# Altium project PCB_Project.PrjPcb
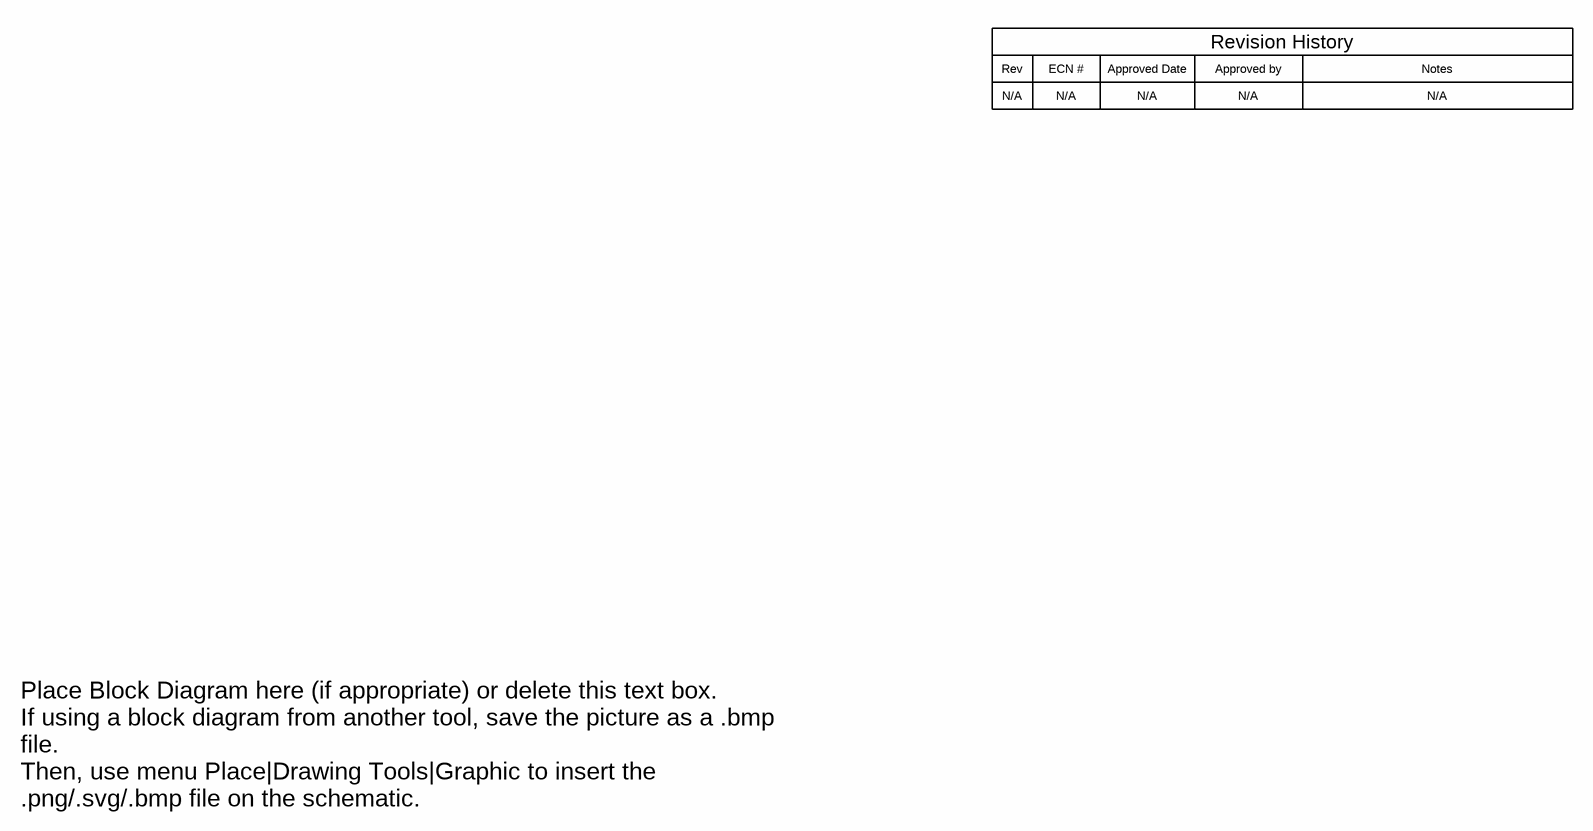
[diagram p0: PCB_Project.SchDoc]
CopyrightYear: 2018; PCB_Layout: Who did the Layout?; PCB_Rev: E1; PRJ_Customer: Public Release; PRJ_Engineer: Enter name of project lead; PRJ_Number: XXX###; PRJ_Title: Change in menu Project|Project Options|Parameters; SCH_Rev: E1; TechSupport: http://www.ti.com/support; TID: N/A
3 sheets, 133 parts. Net scope: flat (ports and power ports of the same name join across sheets).
Board file: PCB_Project.PcbDoc
Sheets:
  PCB_Project.SchDoc
  PCB_Project_BlankSheet.SchDoc
  PCB_Project_Hardware.SchDoc

## Sheet PCB_Project.SchDoc
size 431 x 279 mm; Date: Not shown in title block; ApprovedBy: Not shown in title block; CheckedBy: Not shown in title block; Author: Not shown in title block; CompanyName: Not shown in title block; Engineer: Not shown in title block; Organization: Not shown in title block; Address1: Not shown in title block; Address2: Not shown in title block; Address3: Not shown in title block; Address4: Not shown in title block; DocumentNumber: 1; Revision: Use project parameter SCH_Rev; SheetNumber: 1; SheetTotal: 3; PageSetup: Record=PageOptions¦CenterHorizontal=True¦CenterVertical=True¦PrintScale=1.00¦XCorrection=1.00¦YCorrection=1.00¦PrintKind=0¦BorderSize=5000000¦LeftOffset=0¦BottomOffset=0¦Orientation=2¦PaperLength=1000¦PaperWidth=1000¦Scale=100¦PaperSource=15¦PrintQuality=600¦MediaType=1¦DitherType=10¦PaperKind=Letter¦PrintScaleMode=1

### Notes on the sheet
- Rev
- N/A
- ECN #
- Approved Date
- Approved by
- Revision History
- Notes
- Place Block Diagram here (if appropriate) or delete this text box.
  If using a block diagram from another tool, save the picture as a .bmp file.
  Then, use menu Place|Drawing Tools|Graphic to insert the .png/.svg/.bmp file on the schematic.

## Sheet PCB_Project_BlankSheet.SchDoc
size 431 x 279 mm; Date: Not shown in title block; ApprovedBy: Not shown in title block; CheckedBy: Not shown in title block; Author: Not shown in title block; CompanyName: Not shown in title block; Engineer: Not shown in title block; Organization: Not shown in title block; Address1: Not shown in title block; Address2: Not shown in title block; Address3: Not shown in title block; Address4: Not shown in title block; DocumentNumber: 2; Revision: Use project parameter SCH_Rev; SheetNumber: 2; SheetTotal: 3; PageSetup: Record=PageOptions¦CenterHorizontal=True¦CenterVertical=True¦PrintScale=1.00¦XCorrection=1.00¦YCorrection=1.00¦PrintKind=0¦BorderSize=5000000¦LeftOffset=0¦BottomOffset=0¦Orientation=2¦PaperLength=1000¦PaperWidth=1000¦Scale=100¦PaperSource=15¦PrintQuality=600¦MediaType=1¦DitherType=10¦PaperKind=Letter¦PrintScaleMode=1
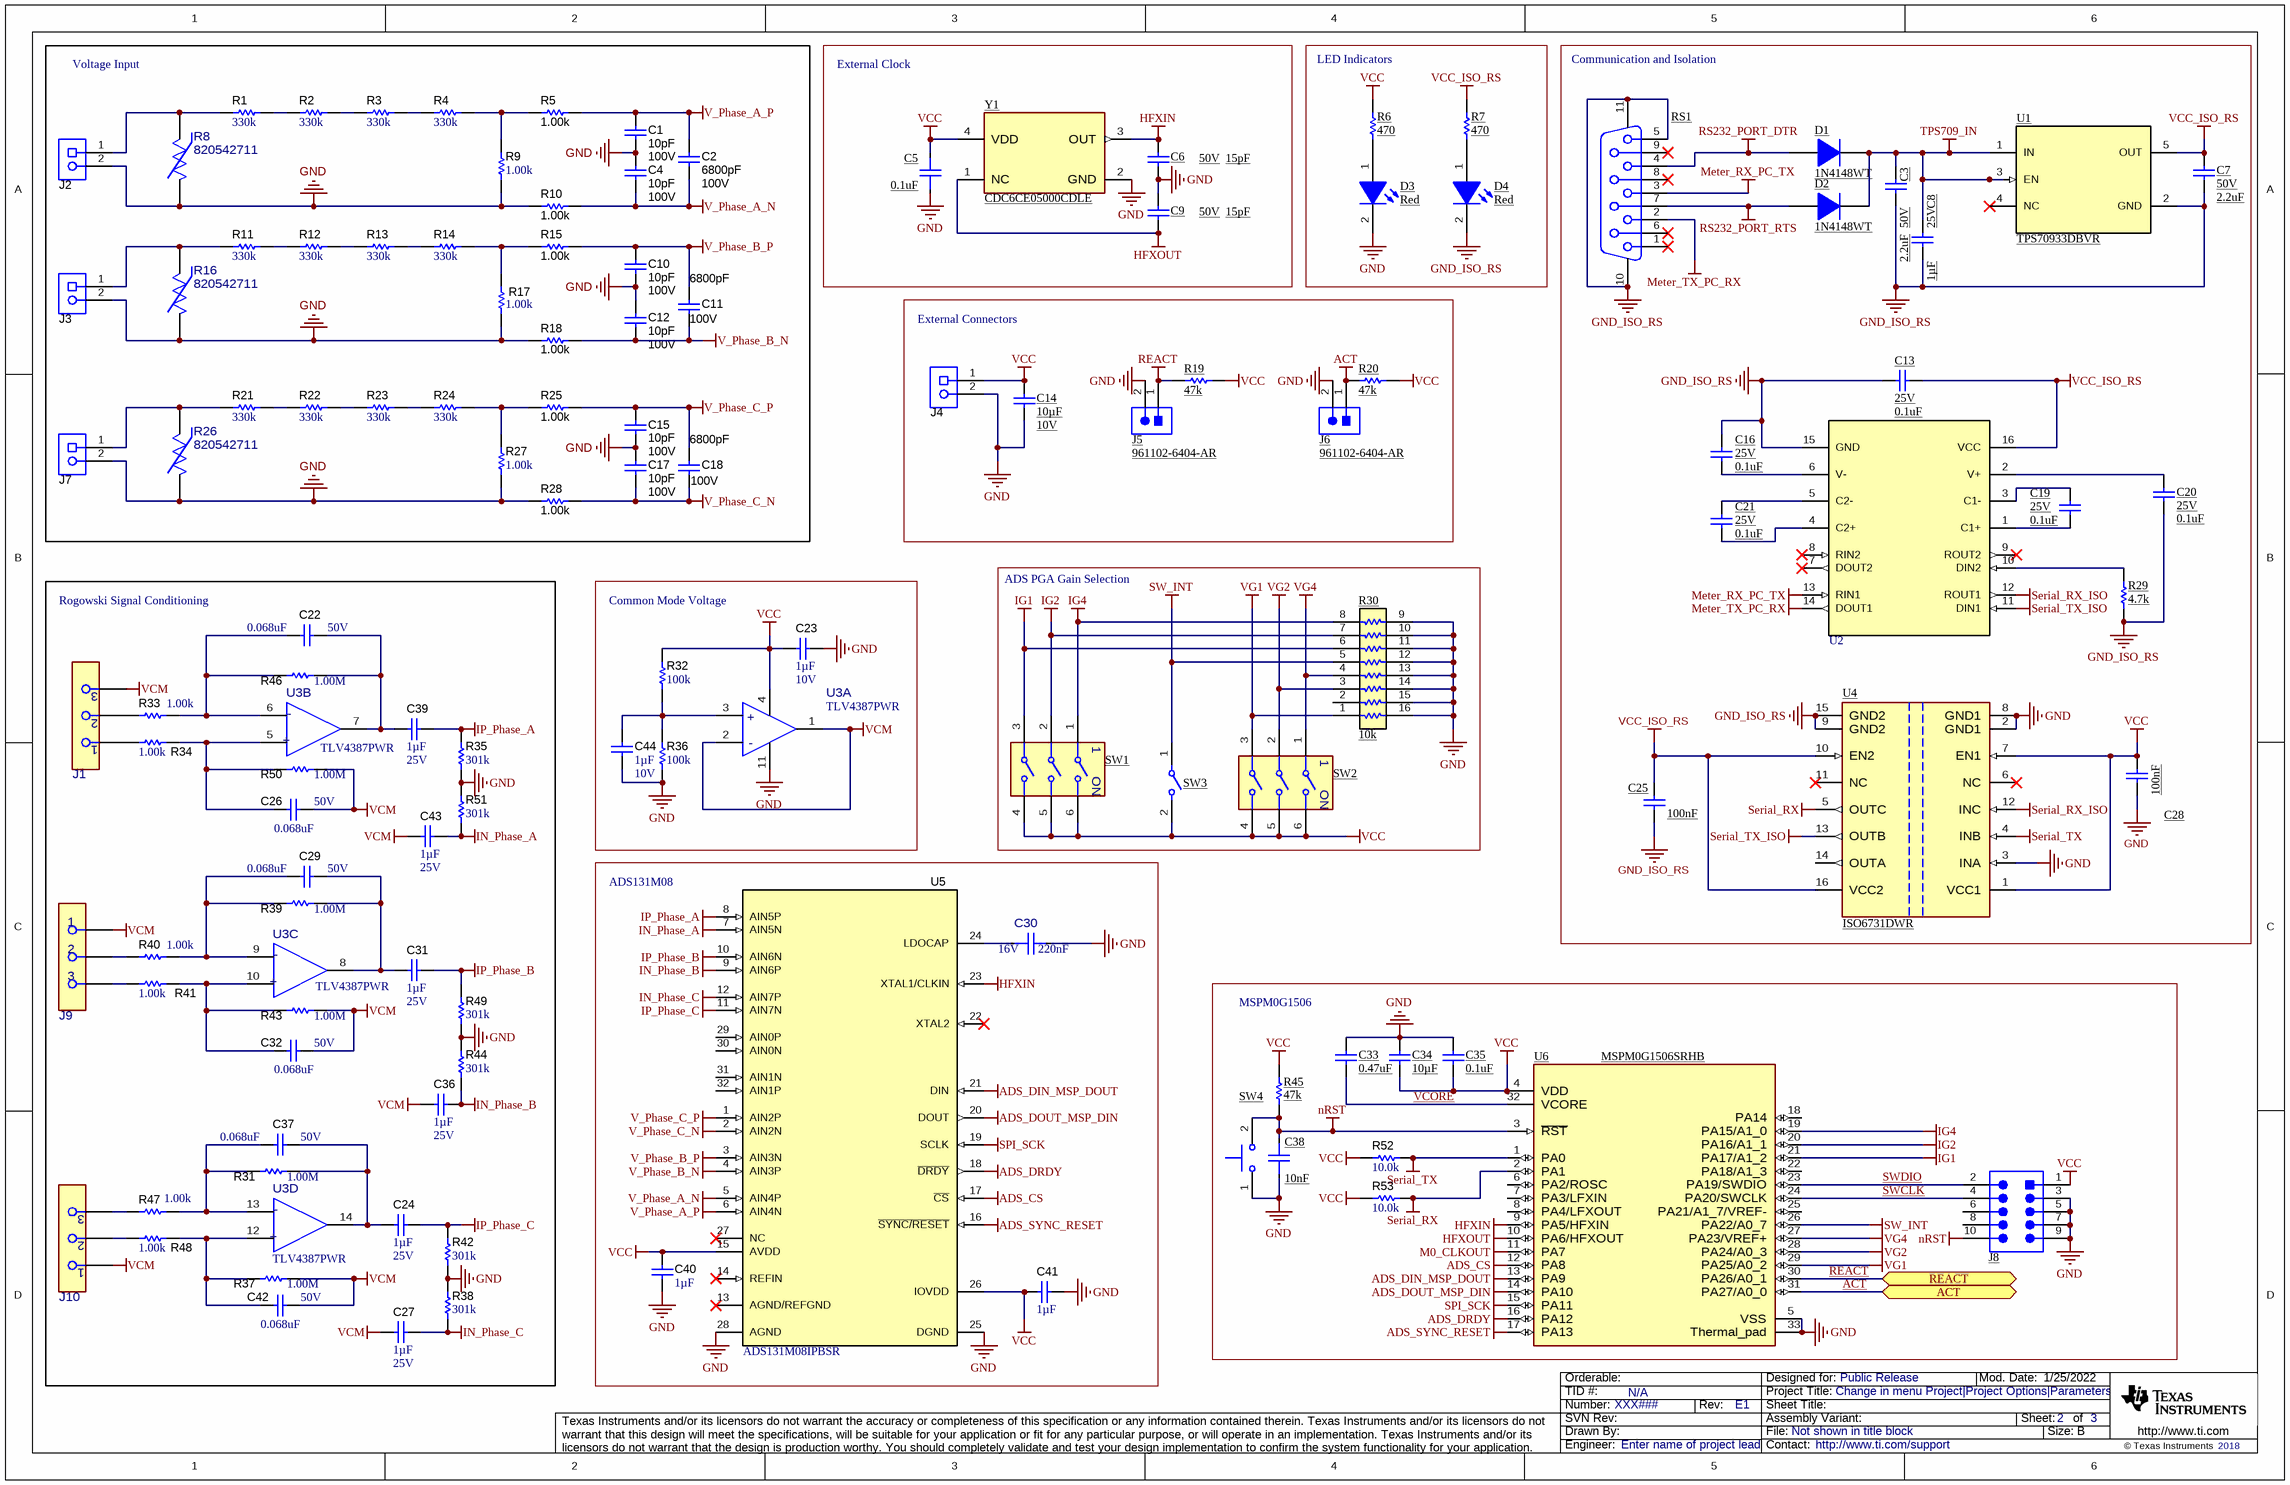
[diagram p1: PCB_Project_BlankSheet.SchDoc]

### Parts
C1  ValueDisplayed: 10pF  VDC_V: 100V  [0603]  (hidden comment: GCM1885C2A100JA16D)
C2  ValueDisplayed: 6800pF  VDC_V: 100V  [0603]  (hidden comment: CGA3EANP02A682J080AC)
C3  VDC_V: 50V  ValueDisplayed: 2.2uF  [0603]  (hidden comment: GRT188R61H225KE13D)
C4  ValueDisplayed: 10pF  VDC_V: 100V  [0603]  (hidden comment: GCM1885C2A100JA16D)
C5  ValueDisplayed: 0.1uF  [FP-885012205018_0402-MFG]  (hidden comment: 885012205018)
C6  VDC_V: 50V  ValueDisplayed: 15pF  [0402]  (hidden comment: GRM1555C1H150JA01D)
C7  VDC_V: 50V  ValueDisplayed: 2.2uF  [0603]  (hidden comment: GRT188R61H225KE13D)
C8  VDC_V: 25V  ValueDisplayed: 1µF  [0603]  (hidden comment: CGA3E1X7R1E105M080AC)
C9  VDC_V: 50V  ValueDisplayed: 15pF  [0402]  (hidden comment: GRM1555C1H150JA01D)
C10  ValueDisplayed: 10pF  VDC_V: 100V  [0603]  (hidden comment: GCM1885C2A100JA16D)
C11  ValueDisplayed: 6800pF  VDC_V: 100V  [0603]  (hidden comment: CGA3EANP02A682J080AC)
C12  ValueDisplayed: 10pF  VDC_V: 100V  [0603]  (hidden comment: GCM1885C2A100JA16D)
C13  VDC_V: 25V  ValueDisplayed: 0.1uF  [0603]  (hidden comment: CGA3E2X8R1E104K080AA)
C14  ValueDisplayed: 10µF  VDC_V: 10V  [0603]  (hidden comment: GRM188R61A106KAALD)
C15  ValueDisplayed: 10pF  VDC_V: 100V  [0603]  (hidden comment: GCM1885C2A100JA16D)
C16  VDC_V: 25V  ValueDisplayed: 0.1uF  [0603]  (hidden comment: CGA3E2X8R1E104K080AA)
C17  ValueDisplayed: 10pF  VDC_V: 100V  [0603]  (hidden comment: GCM1885C2A100JA16D)
C18  ValueDisplayed: 6800pF  VDC_V: 100V  [0603]  (hidden comment: CGA3EANP02A682J080AC)
C19  VDC_V: 25V  ValueDisplayed: 0.1uF  [0603]  (hidden comment: CGA3E2X8R1E104K080AA)
C20  VDC_V: 25V  ValueDisplayed: 0.1uF  [0603]  (hidden comment: CGA3E2X8R1E104K080AA)
C21  VDC_V: 25V  ValueDisplayed: 0.1uF  [0603]  (hidden comment: CGA3E2X8R1E104K080AA)
C22  VDC_V: 50V  ValueDisplayed: 0.068uF  [1206_180]  (hidden comment: GRM31C5C1H683JA01L)
C23  Cap_F: 1µF  VDC_V: 10V  [FP-KAM05CR71A105MH_0402-MFG]  (hidden comment: KAM05CR71A105MH)
C24  Cap_F: 1µF  VDC_V: 25V  [0402]  (hidden comment: GRM155R61E105KA12D)
C25  Cap_F: 100nF  [0603]  (hidden comment: C0603X104K3RACTU)
C26  VDC_V: 50V  ValueDisplayed: 0.068uF  [1206_180]  (hidden comment: GRM31C5C1H683JA01L)
C27  Cap_F: 1µF  VDC_V: 25V  [0402]  (hidden comment: GRM155R61E105KA12D)
C28  Cap_F: 100nF  [0603]  (hidden comment: C0603X104K3RACTU)
C29  VDC_V: 50V  ValueDisplayed: 0.068uF  [1206_180]  (hidden comment: GRM31C5C1H683JA01L)
C30  ValueDisplayed: 220nF  VDC_V: 16V  [FP-CGA2B2X7R1C224K050BE_0402-MFG]  (hidden comment: CGA2B2X7R1C224K050BE)
C31  Cap_F: 1µF  VDC_V: 25V  [0402]  (hidden comment: GRM155R61E105KA12D)
C32  VDC_V: 50V  ValueDisplayed: 0.068uF  [1206_180]  (hidden comment: GRM31C5C1H683JA01L)
C33  ValueDisplayed: 0.47uF  [0603]  (hidden comment: GRM188R61A474KA61D)
C34  ValueDisplayed: 10µF  [0603]  (hidden comment: GRM188R61A106KAALD)
C35  ValueDisplayed: 0.1uF  [0603]  (hidden comment: CGA3E2X8R1E104K080AA)
C36  Cap_F: 1µF  VDC_V: 25V  [0402]  (hidden comment: GRM155R61E105KA12D)
C37  VDC_V: 50V  ValueDisplayed: 0.068uF  [1206_180]  (hidden comment: GRM31C5C1H683JA01L)
C38  ValueDisplayed: 10nF  [FP-885012205050_0402-MFG]  (hidden comment: 885012205050)
C39  Cap_F: 1µF  VDC_V: 25V  [0402]  (hidden comment: GRM155R61E105KA12D)
C40  Cap_F: 1µF  [0603]  (hidden comment: CGA3E1X7R1C105K080AC)
C41  Cap_F: 1µF  [0603]  (hidden comment: CGA3E1X7R1C105K080AC)
C42  VDC_V: 50V  ValueDisplayed: 0.068uF  [1206_180]  (hidden comment: GRM31C5C1H683JA01L)
C43  Cap_F: 1µF  VDC_V: 25V  [0402]  (hidden comment: GRM155R61E105KA12D)
C44  Cap_F: 1µF  VDC_V: 10V  [FP-KAM05CR71A105MH_0402-MFG]  (hidden comment: KAM05CR71A105MH)
D1  1N4148WT  [Fairchild_SOD-523F]
D2  1N4148WT  [Fairchild_SOD-523F]
D3  value Red  [CMD17-21_Red]  (hidden comment: CMD17-21SRC/TR8)
D4  value Red  [CMD17-21_Red]  (hidden comment: CMD17-21SRC/TR8)
J1  691210910003  [FP-691210910003_HDR3-MFG]  (value not drawn)
J2  ED120/2DS  [On-Shore_ED120_2DS]  (value not drawn)
J3  ED120/2DS  [On-Shore_ED120_2DS]  (value not drawn)
J4  ED120/2DS  [On-Shore_ED120_2DS]  (value not drawn)
J5  961102-6404-AR  [3M_961102-6404-AR]
J6  961102-6404-AR  [3M_961102-6404-AR]
J7  ED120/2DS  [On-Shore_ED120_2DS]  (value not drawn)
J8  FTSH-105-01-L-DV-K  [Samtec_FTSH-105-01-x-DV-K]  (value not drawn)
J9  691210910003  [FP-691210910003_HDR3-MFG]  (value not drawn)
J10  691210910003  [FP-691210910003_HDR3-MFG]  (value not drawn)
R1  ValueDisplayed: 330k  [TNPV1206]  (hidden comment: TNPV1206330KBEEN)
R2  ValueDisplayed: 330k  [TNPV1206]  (hidden comment: TNPV1206330KBEEN)
R3  ValueDisplayed: 330k  [TNPV1206]  (hidden comment: TNPV1206330KBEEN)
R4  ValueDisplayed: 330k  [TNPV1206]  (hidden comment: TNPV1206330KBEEN)
R5  ValueDisplayed: 1.00k  [0603]  (hidden comment: RT0603DRD071KL)
R6  ValueDisplayed: 470  [0402]  (hidden comment: RC0402FR-07470RL)
R7  ValueDisplayed: 470  [0402]  (hidden comment: RC0402FR-07470RL)
R8  820542711  [FP-820542711_RADIAL-MFG]
R9  ValueDisplayed: 1.00k  [0603]  (hidden comment: RC0603FR-071KL)
R10  ValueDisplayed: 1.00k  [0603]  (hidden comment: RT0603DRD071KL)
R11  ValueDisplayed: 330k  [TNPV1206]  (hidden comment: TNPV1206330KBEEN)
R12  ValueDisplayed: 330k  [TNPV1206]  (hidden comment: TNPV1206330KBEEN)
R13  ValueDisplayed: 330k  [TNPV1206]  (hidden comment: TNPV1206330KBEEN)
R14  ValueDisplayed: 330k  [TNPV1206]  (hidden comment: TNPV1206330KBEEN)
R15  ValueDisplayed: 1.00k  [0603]  (hidden comment: RT0603DRD071KL)
R16  820542711  [FP-820542711_RADIAL-MFG]
R17  ValueDisplayed: 1.00k  [0603]  (hidden comment: RC0603FR-071KL)
R18  ValueDisplayed: 1.00k  [0603]  (hidden comment: RT0603DRD071KL)
R19  ValueDisplayed: 47k  [0402]  (hidden comment: CRCW040247K0JNED)
R20  ValueDisplayed: 47k  [0402]  (hidden comment: CRCW040247K0JNED)
R21  ValueDisplayed: 330k  [TNPV1206]  (hidden comment: TNPV1206330KBEEN)
R22  ValueDisplayed: 330k  [TNPV1206]  (hidden comment: TNPV1206330KBEEN)
R23  ValueDisplayed: 330k  [TNPV1206]  (hidden comment: TNPV1206330KBEEN)
R24  ValueDisplayed: 330k  [TNPV1206]  (hidden comment: TNPV1206330KBEEN)
R25  ValueDisplayed: 1.00k  [0603]  (hidden comment: RT0603DRD071KL)
R26  820542711  [FP-820542711_RADIAL-MFG]
R27  ValueDisplayed: 1.00k  [0603]  (hidden comment: RC0603FR-071KL)
R28  ValueDisplayed: 1.00k  [0603]  (hidden comment: RT0603DRD071KL)
R29  ValueDisplayed: 4.7k  [0603]  (hidden comment: CRCW06034K70JNEA)
R30  ValueDisplayed: 10k  [RESCAXS_EXB-2HV]  (hidden comment: EXB2HV103JV)
R31  ValueDisplayed: 1.00M  [0402]  (hidden comment: RMCF0402FT1M00)
R32  ValueDisplayed: 100k  [0402]  (hidden comment: RG1005P-104-B-T5)
R33  ValueDisplayed: 1.00k  [0402]  (hidden comment: ERA-2AEB102X)
R34  ValueDisplayed: 1.00k  [0402]  (hidden comment: ERA-2AEB102X)
R35  ValueDisplayed: 301k  [0402]  (hidden comment: CRCW0402301KFKED)
R36  ValueDisplayed: 100k  [0402]  (hidden comment: RG1005P-104-B-T5)
R37  ValueDisplayed: 1.00M  [0402]  (hidden comment: RMCF0402FT1M00)
R38  ValueDisplayed: 301k  [0402]  (hidden comment: CRCW0402301KFKED)
R39  ValueDisplayed: 1.00M  [0402]  (hidden comment: RMCF0402FT1M00)
R40  ValueDisplayed: 1.00k  [0402]  (hidden comment: ERA-2AEB102X)
R41  ValueDisplayed: 1.00k  [0402]  (hidden comment: ERA-2AEB102X)
R42  ValueDisplayed: 301k  [0402]  (hidden comment: CRCW0402301KFKED)
R43  ValueDisplayed: 1.00M  [0402]  (hidden comment: RMCF0402FT1M00)
R44  ValueDisplayed: 301k  [0402]  (hidden comment: CRCW0402301KFKED)
R45  ValueDisplayed: 47k  [0402]  (hidden comment: CRCW040247K0JNED)
R46  ValueDisplayed: 1.00M  [0402]  (hidden comment: RMCF0402FT1M00)
R47  ValueDisplayed: 1.00k  [0402]  (hidden comment: ERA-2AEB102X)
R48  ValueDisplayed: 1.00k  [0402]  (hidden comment: ERA-2AEB102X)
R49  ValueDisplayed: 301k  [0402]  (hidden comment: CRCW0402301KFKED)
R50  ValueDisplayed: 1.00M  [0402]  (hidden comment: RMCF0402FT1M00)
R51  ValueDisplayed: 301k  [0402]  (hidden comment: CRCW0402301KFKED)
R52  ValueDisplayed: 10.0k  [0402]  (hidden comment: PCF0402-12-10KBT1)
R53  ValueDisplayed: 10.0k  [0402]  (hidden comment: PCF0402-12-10KBT1)
RS1  2-5747706-0  [TE_2-5747706-0]  (value not drawn)
SW1  416131160803  [FP-416131160803_SMT_SW_5MM8_4MM98-MFG]  (value not drawn)
SW2  416131160803  [FP-416131160803_SMT_SW_5MM8_4MM98-MFG]  (value not drawn)
SW3  TDA01H0SB1R  [FP-TDA01H0SB1R_SMT_SW_2MM40_6MM20-MFG]  (value not drawn)
SW4  TL1015AF160QG  [SW_TL1015AF160QG]  (value not drawn)
U1  TPS70933DBVR  [DBV0005A_N]
U2  TRS3232EIDBR  [DB0016A_L]  (value not drawn)
U3  TLV4387PWR  [PW0014A-MFG]  (parts A,B,C,D of 4)
U4  ISO6731DWR  [DW0016A-MFG]
U5  ADS131M08IPBSR  [PBS0032A_N]
U6  MSPM0G1506SRHB  [RHB0032N-MFG]
Y1  PartNumber: CDC6CE05000CDLE  [DLE0004A-MFG]  (hidden comment: CDC6CE008192ADLE)

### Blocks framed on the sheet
Voltage Input: C1 C2 C4 C10-C12 C15 C17 C18 J2 J3 J7 R1-R5 R8-R18 R21-R28
External Clock: C5 C6 C9 Y1
LED Indicators: D3 D4 R6 R7
Communication and Isolation: C3 C7 C8 C13 C16 C19-C21 C25 C28 D1 D2 R29 RS1 U1 U2 U4
External Connectors: C14 J4-J6 R19 R20
Rogowski Signal Conditioning: C22 C24 C26 C27 C29 C31 C32 C36 C37 C39 C42 C43 J1 J9 J10 R31 R33-R35 R37-R44 R46-R51 U3
Common Mode Voltage: C23 C44 R32 R36 U3
ADS PGA Gain Selection: R30 SW1-SW3
ADS131M08: C30 C40 C41 U5
MSPM0G1506: C33-C35 C38 J8 R45 R52 R53 SW4 U6

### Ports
ACT (bidir), REACT (bidir)

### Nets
ACT: J6.1 R20.1 U6.31(PA27/A0_0) ; port ACT
ADS_CS: U5.17(~{CS}) U6.12(PA8)
ADS_DIN_MSP_DOUT: U5.21(DIN) U6.13(PA9)
ADS_DOUT_MSP_DIN: U5.20(DOUT) U6.14(PA10)
ADS_DRDY: U5.18(~{DRDY}) U6.16(PA12)
ADS_SYNC_RESET: U5.16(~{SYNC/RESET}) U6.17(PA13)
GND: C1.2 C4.1 C5.1 C6.2 C9.1 C10.2 C12.1 C14.2 C15.2 C17.1 C23.2 C28.2 C30.2 C33.1 C34.1 C35.1 C38.1 C40.1 C41.1 C44.2 D3.2(K) J2.2 J3.2 J4.2 J5.2 J6.2 J7.2 J8.3 J8.5 J8.7 J8.9 R8.1 R9.1 R10.1 R16.1 R17.1 R18.1 R26.1 R27.1 R28.1 R30.9 R30.10 R30.11 R30.12 R30.13 R30.14 R30.15 R30.16 R35.1 R36.1 R38.2 R42.1 R44.2 R49.1 R51.2 SW4.1 U3.11(V-) U4.2(GND1) U4.3(INA) U4.8(GND1) U5.25(DGND) U5.28(AGND) U6.5(VSS) U6.33(Thermal_pad) Y1.2(GND)
GND_ISO_RS: C3.2 C7.2 C8.2 C13.1 C16.1 C20.1 C25.2 D4.2(K) R29.1 RS1.5 RS1.10 RS1.11 U1.2(GND) U2.15(GND) U4.9(GND2) U4.15(GND2)
HFXIN: C6.1 U5.23(XTAL1/CLKIN) U6.9(PA5/HFXIN) Y1.3(OUT)
HFXOUT: C9.2 U6.10(PA6/HFXOUT) Y1.1(NC)
IG1: R30.6 SW1.3 U6.21(PA17/A1_2)
IG2: R30.7 SW1.2 U6.20(PA16/A1_1)
IG4: R30.8 SW1.1 U6.19(PA15/A1_0)
IN_Phase_A: C43.2 R51.1 U5.7(AIN5N)
IN_Phase_B: C36.2 R44.1 U5.9(AIN6P)
IN_Phase_C: C27.2 R38.1 U5.12(AIN7P)
IP_Phase_A: C39.2 R35.2 U5.8(AIN5P)
IP_Phase_B: C31.2 R49.2 U5.10(AIN6N)
IP_Phase_C: C24.2 R42.2 U5.11(AIN7N)
M0_CLKOUT: U6.11(PA7)
Meter_RX_PC_TX: RS1.3 U2.13(RIN1)
Meter_TX_PC_RX: RS1.2 U2.14(DOUT1)
nRST: C38.2 J8.10 R45.1 SW4.2 U6.3(~{RST})
REACT: J5.1 R19.1 U6.30(PA26/A0_1) ; port REACT
RS232_PORT_DTR: D1.2(A) RS1.4
RS232_PORT_RTS: D2.2(A) RS1.7
Serial_RX: R53.1 U4.5(OUTC) U6.2(PA1)
Serial_RX_ISO: U2.12(ROUT1) U4.12(INC)
Serial_TX: R52.1 U4.4(INB) U6.1(PA0)
Serial_TX_ISO: U2.11(DIN1) U4.13(OUTB)
SPI_SCK: U5.19(SCLK) U6.15(PA11)
SW_INT: R30.5 SW3.1 U6.26(PA22/A0_7)
TPS709_IN: C3.1 C8.1 D1.1(K) D2.1(K) U1.1(IN) U1.3(EN)
V_Phase_A_N: C2.2 C4.2 R10.2 U5.5(AIN4P)
V_Phase_A_P: C1.1 C2.1 R5.2 U5.6(AIN4N)
V_Phase_B_N: C11.2 C12.2 R18.2 U5.4(AIN3P)
V_Phase_B_P: C10.1 C11.1 R15.2 U5.3(AIN3N)
V_Phase_C_N: C17.2 C18.2 R28.2 U5.2(AIN2N)
V_Phase_C_P: C15.1 C18.1 R25.2 U5.1(AIN2P)
VCC: C5.2 C14.1 C23.1 C28.1 C34.2 C35.2 C40.2 C41.2 J4.1 J8.1 R6.2 R19.2 R20.2 R32.2 R45.2 R52.2 R53.2 SW1.4 SW1.5 SW1.6 SW2.4 SW2.5 SW2.6 SW3.2 U3.4(V+) U4.1(VCC1) U4.7(EN1) U5.15(AVDD) U5.26(IOVDD) U6.4(VDD) Y1.4(VDD)
VCC_ISO_RS: C7.1 C13.2 C25.1 R7.2 U1.5(OUT) U2.16(VCC) U4.10(EN2) U4.16(VCC2)
VCM: C26.1 C27.1 C32.1 C36.1 C42.1 C43.1 J1.3 J9.1 J10.1 R37.2 R43.2 R50.2 U3.1(OUT_A) U3.2(-IN_A)
VG1: R30.1 SW2.3 U6.29(PA25/A0_2)
VG2: R30.3 SW2.2 U6.28(PA24/A0_3)
VG4: R30.4 SW2.1 U6.27(PA23/VREF+)
SWCLK: J8.4 U6.24(PA20/SWCLK)
SWDIO: J8.2 U6.23(PA19/SWDIO)
VCORE: C33.2 U6.32(VCORE)
NetC16_2: C16.2 U2.6(V-)
NetC19_1: C19.1 U2.3(C1-)
NetC19_2: C19.2 U2.1(C1+)
NetC20_2: C20.2 U2.2(V+)
NetC21_1: C21.1 U2.5(C2-)
NetC21_2: C21.2 U2.4(C2+)
NetC22_1: C22.1 C39.1 R46.2 U3.7(OUT_B)
NetC22_2: C22.2 R33.2 R46.1 U3.6(-IN_B)
NetC24_1: C24.1 C37.1 R31.2 U3.14(OUT_D)
NetC26_2: C26.2 R34.2 R50.1 U3.5(+IN_B)
NetC29_1: C29.1 C31.1 R39.2 U3.8(OUT_C)
NetC29_2: C29.2 R39.1 R40.2 U3.9(-IN_C)
NetC30_1: C30.1 U5.24(LDOCAP)
NetC32_2: C32.2 R41.2 R43.1 U3.10(+IN_C)
NetC37_2: C37.2 R31.1 R47.2 U3.13(-IN_D)
NetC42_2: C42.2 R37.1 R48.2 U3.12(+IN_D)
NetC44_1: C44.1 R32.1 R36.2 U3.3(+IN_A)
NetD3_1: D3.1(A) R6.1
NetD4_1: D4.1(A) R7.1
NetJ1_1: J1.1 R34.1
NetJ1_2: J1.2 R33.1
NetJ2_1: J2.1 R1.2 R8.2
NetJ3_1: J3.1 R11.2 R16.2
NetJ7_1: J7.1 R21.2 R26.2
NetJ9_2: J9.2 R40.1
NetJ9_3: J9.3 R41.1
NetJ10_2: J10.2 R48.1
NetJ10_3: J10.3 R47.1
NetR1_1: R1.1 R2.2
NetR2_1: R2.1 R3.2
NetR3_1: R3.1 R4.2
NetR4_1: R4.1 R5.1 R9.2
NetR11_1: R11.1 R12.2
NetR12_1: R12.1 R13.2
NetR13_1: R13.1 R14.2
NetR14_1: R14.1 R15.1 R17.2
NetR21_1: R21.1 R22.2
NetR22_1: R22.1 R23.2
NetR23_1: R23.1 R24.2
NetR24_1: R24.1 R25.1 R27.2
NetR29_2: R29.2 U2.10(DIN2)

Not connected (* = marked no-connect by the designer): J8 6 8; R30 2; RS1 1* 6* 8* 9*; U1 4(NC)*; U2 7(DOUT2)* 8(RIN2)* 9(ROUT2)*; U4 6(NC)* 11(NC)* 14(OUTA); U5 13(AGND/REFGND)* 14(REFIN)* 22(XTAL2)* 27(NC)* 29(AIN0P) 30(AIN0N) 31(AIN1N) 32(AIN1P); U6 6(PA2/ROSC) 7(PA3/LFXIN) 8(PA4/LFXOUT) 18(PA14) 22(PA18/A1_3) 25(PA21/A1_7/VREF-)

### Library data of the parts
C1 C4 C10 C12 C15 C17 = CMP-0084283-1: CAP, CERM, 10 pF, 100 V,+/- 5%, C0G/NP0, AEC-Q200 Grade 1, 0603; Manufacturer: MuRata; TaMax_C: 125°C; SizeX_mm: 1.6; SizeY_mm: 0.8; SizeArea_mm2: 1.28; Polarized: N; AEC Category: Q200; SizeAreaWB_mm2: 4.68; AEC Qualified: Y; SizeZ_mm: 1; Value: 10pF; U/M: EA; TaMin_C: -55°C
C2 C11 C18 = CMP-0084514-1: CAP, CERM, 6800 pF, 100 V,+/- 5%, C0G/NP0, AEC-Q200 Grade 0, 0603; Manufacturer: TDK; U/M: EA; SizeAreaWB_mm2: 4.68; Value: 6800pF; Polarized: N; AEC Qualified: Y; TaMax_C: 150°C; AEC Grade: 0; SizeX_mm: 1.6; Cap_F: 6.8nF; TaMin_C: -55°C; SizeZ_mm: 1; SizeY_mm: 0.8; AEC Category: Q200; SizeArea_mm2: 1.28
C3 C7 = CMP-0007502-5: CAP, CERM, 2.2 uF, 50 V, +/- 10%, X5R, AEC-Q200 Grade 3, 0603; Manufacturer: MuRata; TaMin_C: -55°C; Polarized: N; SizeAreaWB_mm2: 4.68; Value1: Unknown; U/M: EA; Value: 2.2uF; TaMax_C: 85°C; SizeZ_mm: 1; SizeX_mm: 1.6; SizeY_mm: 0.8; SizeArea_mm2: 1.28; CompType: Capacitor; AEC Qualified: Y; Cap_F: 2.2µF; AEC Grade: 3; AEC Category: Q200
C5 = CMP-0090362-1: 0.1µF ±10% 10V Ceramic Capacitor X7R 0402 (1005 Metric); Manufacturer: Wurth Electronics; AEC Qualified: No; Value: 100nF; SizeZ_mm: 0.55mm; TempCo: 15%
C6 C9 = CMP-0006420-2: CAP, CERM, 15 pF, 50 V, +/- 5%, C0G/NP0, 0402; Manufacturer: MuRata; TaMin_C: -55°C; Polarized: N; SizeAreaWB_mm2: 3; Value1: Unknown; U/M: EA; Value: 15pF; TaMax_C: 125°C; SizeZ_mm: 0.6; SizeX_mm: 1; SizeY_mm: 0.5; AEC Category: Q200
C8 = CMP-0082113-1: CAP, CERM, 1 µF, 25 V,+/- 20%, X7R, AEC-Q200 Grade 1, 0603; Manufacturer: TDK; SizeAreaWB_mm2: 4.68; SizeArea_mm2: 1.28; AEC Qualified: Y; AEC Category: Q200; Value: 1uF; TaMax_C: 125°C; SizeZ_mm: 1; Polarized: N; TaMin_C: -55°C; SizeY_mm: 0.8; U/M: EA; SizeX_mm: 1.6
C13 C16 C19-C21 = CMP-0007090-4: CAP, CERM, 0.1 uF, 25 V, +/- 10%, X8R, AEC-Q200 Grade 0, 0603; Manufacturer: TDK; TaMin_C: -55°C; Polarized: N; SizeAreaWB_mm2: 4.68; Value1: Unknown; U/M: EA; Value: 0.1uF; TaMax_C: 150°C; SizeZ_mm: 1; SizeX_mm: 1.6; SizeY_mm: 0.8; SizeArea_mm2: 1.28; AEC Qualified: Y; Cap_F: 100nF; AEC Grade: 0; AEC Category: Q200
C14 = CMP-0086193-1: CAP, CERM, 10 µF, 10 V,+/- 10%, X5R, 0603; Manufacturer: MuRata; SizeArea_mm2: 1.28; SizeY_mm: 0.8; TaMax_C: 85°C; TaMin_C: -55°C; Polarized: N; SizeAreaWB_mm2: 4.68; SizeZ_mm: 1; SizeX_mm: 1.6; AEC Category: Q200; U/M: EA; Value: 10uF
C22 C26 C29 C32 C37 C42 = CMP-0008921-2: CAP, CERM, 0.068 uF, 50 V, +/- 5%, C0G/NP0, 1206; Manufacturer: MuRata; TaMin_C: -55°C; ESR_ohm: 10m; Polarized: N; SizeAreaWB_mm2: 10.92; Value1: 0.01 ohm; U/M: EA; TaMax_C: 125°C; SizeZ_mm: 1.8; SizeX_mm: 3.2; SizeY_mm: 1.6; Cap_Case: 1206; SizeArea_mm2: 5.12; Cap_F: 68nF; IRMS_A: 900mA; AEC Category: Q200
C23 C44 = CMP-0124278-2: 1 µF ±20% 10V Ceramic Capacitor X7R 0402 (1005 Metric); Manufacturer: KYOCERA AVX; TempCo: 15%; Value: 1µF; SizeZ_mm: 0.7mm; AEC Qualified: Yes; AEC Grade: Grade 1; ValueDisplayed: 1uF
C24 C27 C31 C36 C39 C43 = CMP-0006608-2: CAP, CERM, 1 uF, 25 V, +/- 10%, X5R, 0402; Manufacturer: MuRata; TaMin_C: -55°C; Polarized: N; SizeAreaWB_mm2: 3; U/M: EA; Value: 1uF; TaMax_C: 85°C; SizeZ_mm: 0.6; SizeX_mm: 1; SizeY_mm: 0.5; AEC Category: Q200; Value1: Unknown
C25 C28 = CMP-0006979-5: CAP, CERM, 0.1 uF, 25 V, +/- 10%, X7R, 0603; Manufacturer: Kemet; TaMin_C: -55°C; Polarized: N; SizeAreaWB_mm2: 4.68; Value1: Unknown; U/M: EA; Value: 0.1uF; TaMax_C: 125°C; SizeZ_mm: 1; SizeX_mm: 1.6; SizeY_mm: 0.8; Value2: 25V; SizeArea_mm2: 1.28; AEC Category: Q200
C30 = CMP-0092769-1: Cap Ceramic 220nF 16V X7R 10% Pad SMD 0402 +125°C Automotive T/R; Manufacturer: TDK Corporation; Tolerance_%: 0.1%; AEC Qualified: Yes; AEC Grade: Grade 1; TempCo: 15%; SizeZ_mm: 0.55mm
C33 = CMP-0007328-5: CAP, CERM, 0.47 uF, 10 V, +/- 10%, X5R, 0603; Manufacturer: MuRata; TaMin_C: -55°C; Polarized: N; SizeAreaWB_mm2: 4.68; Value1: Unknown; U/M: EA; Value: 0.47uF; TaMax_C: 85°C; SizeZ_mm: 1; SizeX_mm: 1.6; SizeY_mm: 0.8; Value2: 10V; SizeArea_mm2: 1.28; Cap_F: 470nF; AEC Category: Q200
C34 = CMP-0086193-1: CAP, CERM, 10 µF, 10 V,+/- 10%, X5R, 0603; Manufacturer: MuRata; SizeArea_mm2: 1.28; SizeY_mm: 0.8; TaMax_C: 85°C; TaMin_C: -55°C; VDC_V: 10V; Polarized: N; SizeAreaWB_mm2: 4.68; SizeZ_mm: 1; SizeX_mm: 1.6; AEC Category: Q200; U/M: EA; Value: 10uF
C35 = CMP-0007090-4: CAP, CERM, 0.1 uF, 25 V, +/- 10%, X8R, AEC-Q200 Grade 0, 0603; Manufacturer: TDK; TaMin_C: -55°C; Polarized: N; SizeAreaWB_mm2: 4.68; Value1: Unknown; U/M: EA; Value: 0.1uF; TaMax_C: 150°C; SizeZ_mm: 1; SizeX_mm: 1.6; SizeY_mm: 0.8; Value2: 25V; SizeArea_mm2: 1.28; AEC Qualified: Y; Cap_F: 100nF; AEC Grade: 0; AEC Category: Q200
C38 = CMP-0090363-1: 10000pF ±10% 25V Ceramic Capacitor X7R 0402 (1005 Metric); Manufacturer: Wurth Electronics; SizeZ_mm: 0.55mm; AEC Qualified: No; Value: 10nF; TempCo: 15%
C40 C41 = CMP-0079607-1: CAP, CERM, 1 µF, 16 V,+/- 10%, X7R, AEC-Q200 Grade 1, 0603; Manufacturer: TDK; TaMin_C: -55°C; Polarized: N; SizeAreaWB_mm2: 4.68; U/M: EA; Value: 1uF; TaMax_C: 125°C; SizeZ_mm: 1; SizeX_mm: 1.6; SizeY_mm: 0.8; Value2: 16V; SizeArea_mm2: 1.28; AEC Qualified: Y; AEC Category: Q200
D1 D2 = CMP-0076982-2: Diode, Switching, 75 V, 0.3 A, SOD-523F; Manufacturer: Fairchild Semiconductor; TJmax_C: 150°C; AEC Category: Q101; SizeX_mm: 1.6; Value: 75V; Io_A: 300mA; Value1: 0.3A; Green_REACh: Incomplete; SizeZ_mm: 0.7; Green_Lifecycle: Not Set; SizeArea_mm2: 1.28; SizeAreaWB_mm2: 4.68; SizeY_mm: 0.8
D3 D4 = CMP-0084855-1: LED, Red, SMD; Manufacturer: Visual Communications Company, LLC; SizeX_mm: 2; SizeArea_mm2: 2.5; SizeAreaWB_mm2: 6.75; Angle: 140; Value2: 1.7V; Ir_A: 100µA; Value1: 0.1W; SizeY_mm: 1.25; Io_A: 20mA; Tjmax_C: 85°C; Power_TotalModule: 100mW; SizeZ_mm: 1.2; Vr_V: 5V
J1 J9 J10 = CMP-0123060-1: 3 Position Wire to Board Terminal Block Horizontal with Board 0.100" (2.54mm) Through Hole; Manufacturer: Wurth; Current_A: 6A; Voltage_V: 150V; Row_Count: 1; ContactFinish: Tin,Nickel; AEC Qualified: No; Is Female: yes; Max Wire Gauge: 18; Min Wire Gauge: 30; SizeZ_mm: 8.8mm
J2-J4 J7 = CMP-0074910-1: Terminal Block, 5.08 mm, 2x1, Brass, TH; Manufacturer: On-Shore Technology; Cert_VDE: Y; CNHeader: False; Current_A: 15A; Green_Lifecycle: Not Set; Shrouded: N; Gender: Female; Green_REACh: Incomplete; Voltage_V: 300V; Row_Count: 1; Pitch_mm: 5.08; CT: True
J5 J6 = CMP-0075197-1: Header, 2.54mm, 2x1, TH; Manufacturer: 3M; CNHeader: True; Current_A: 2A; Green_Lifecycle: Active; Shrouded: N; Gender: Male; Green_REACh: Passed; Voltage_V: 1kV; Row_Count: 1; Pitch_mm: 2.54; ContactFinish: Gold; CT: False; Cert_UL: Y
J8 = CMP-0075634-1: Header(Shrouded), 1.27mm, 5x2, Gold, SMT; Manufacturer: Samtec; Pitch_mm: 1.27; Gender: Male; Cert_CSA: Y; Current_A: 3.3A; CT: False; Row_Count: 2
R1-R4 R11-R14 R21-R24 = CMP-0018811-2: RES, 330 k, 0.1%, 1 W, 1206; Manufacturer: Vishay Draloric; Power_W: 1W; TempCo: 25 ppm/C; U/M: EA; Value: 330k; SizeX_mm: 3.2; SizeY_mm: 1.6; SizeZ_mm: 0.65; SizeArea_mm2: 5.12; AEC Qualified: N; VDC_V: 700V; AEC Category: Q200
R5 R10 R15 R18 R25 R28 = CMP-0084355-1: RES, 1.00 k, 0.5%, 0.1 W, 0603; Manufacturer: Yageo; SizeArea_mm2: 1.28; Value2: 0.1W; Res_ohm: 1k; Power_W: 100mW; EIA_Code: E192; SizeAreaWB_mm2: 4.68; TempCo: 25 ppm/C; SizeY_mm: 0.8; SizeX_mm: 1.6; AEC Qualified: N; Value_Code: 1k00; SizeZ_mm: 1; AEC Category: Q200; Value: 1.00k
R6 R7 = CMP-0026736-1: RES, 470, 1%, 0.063 W, 0402; Manufacturer: Yageo America; Power_W: 63mW; TempCo: 100 ppm/C; Value_Code: 470R; U/M: EA; Value: 470; SizeX_mm: 1; SizeY_mm: 0.5; SizeZ_mm: 0.6; Value2: 0.063W; AEC Qualified: N; VDC_V: 50V; AEC Category: Q200
R8 R16 R26 = CMP-0126415-1: 430 V 4.5 kA Varistor 1 Circuit Through Hole Disc 14mm; Manufacturer: Wurth Electronics; SizeZ_mm: 20mm; AEC Qualified: No; Cap_F: 450pF; Clamping Voltage: 710V; Varistor Voltage: 430V; VDC_V: 350V; Voltage Tolerance: 10%
R9 R17 R27 = CMP-0022895-5: RES, 1.00 k, 1%, 0.1 W, 0603; Manufacturer: Yageo; Power_W: 100mW; TempCo: 100 ppm/C; Value_Code: 1k00; Value: 1.00k; EIA_Code: E96; Res_ohm: 1k; SizeX_mm: 1.6; SizeY_mm: 0.8; SizeZ_mm: 1; Value2: 0.1W; SizeArea_mm2: 1.28; AEC Qualified: N; VDC_V: 75V; AEC Category: Q200; SizeAreaWB_mm2: 4.68
R19 R20 R45 = CMP-0026935-3: RES, 47 k, 5%, 0.063 W, AEC-Q200 Grade 0, 0402; Manufacturer: Vishay-Dale; Power_W: 63mW; TempCo: 200 ppm/C; Value_Code: 47k0; Value: 47k; EIA_Code: E24; SizeX_mm: 1; SizeY_mm: 0.5; SizeZ_mm: 0.6; Value2: 0.063W; AEC Qualified: Y; VDC_V: 50V; AEC Category: Q200; AEC Grade: 0
R29 = CMP-0025817-4: RES, 4.7 k, 5%, 0.1 W, AEC-Q200 Grade 0, 0603; Manufacturer: Vishay-Dale; Power_W: 100mW; TempCo: 200 ppm/C; Value_Code: 4k70; Value: 4.7k; EIA_Code: E24; SizeX_mm: 1.6; SizeY_mm: 0.8; SizeZ_mm: 1; Value2: 0.1W; SizeArea_mm2: 1.28; AEC Qualified: Y; VDC_V: 75V; AEC Category: Q200; AEC Grade: 0
R30 = CMP-0081256-1: RES, 10 k, 5%, 0.063 W, AEC-Q200 Grade 1, Resistor Array - 8x1; Manufacturer: Panasonic; Value_Code: 10k0; AEC Qualified: Y; AEC Category: Q200; Value: 10k; EIA_Code: E24; TempCo: 200 ppm/C; AEC Grade: 1; Power_W: 63mW; VDC_V: 25V; Value2: 0.063W
R31 R37 R39 R43 R46 R50 = CMP-0026757-1: RES, 1.00 M, 1%, 0.063 W, AEC-Q200 Grade 0, 0402; Manufacturer: Stackpole Electronics Inc; Power_W: 63mW; TempCo: 100 ppm/C; Value_Code: 1M00; Value: 1.00Meg; EIA_Code: E96; Res_ohm: 1M; SizeX_mm: 1; SizeY_mm: 0.5; SizeZ_mm: 0.6; Value2: 0.063W; AEC Qualified: Y; VDC_V: 50V; AEC Category: Q200; AEC Grade: 0; U/M: EA
R32 R36 = CMP-0026815-1: RES, 100 k, 0.1%, 0.063 W, 0402; Manufacturer: Susumu Co Ltd; Power_W: 63mW; TempCo: 25 ppm/C; Value: 100k; EIA_Code: E192; SizeX_mm: 1; SizeY_mm: 0.5; SizeZ_mm: 0.6; Value2: 0.063W; AEC Category: Q200; U/M: EA
R33 R34 R40 R41 R47 R48 = CMP-0026770-1: RES, 1.00 k, 0.1%, 0.063 W, 0402; Manufacturer: Panasonic; Power_W: 63mW; TempCo: 25 ppm/C; Value_Code: 1k00; Value: 1.00k; EIA_Code: E192; Res_ohm: 1k; SizeX_mm: 1; SizeY_mm: 0.5; SizeZ_mm: 0.6; Value2: 0.063W; AEC Category: Q200; VDC_V: 50V; U/M: EA
R35 R38 R42 R44 R49 R51 = CMP-0026280-2: RES, 301 k, 1%, 0.063 W, AEC-Q200 Grade 0, 0402; Manufacturer: Vishay-Dale; Power_W: 63mW; TempCo: 100 ppm/C; Value: 301k; EIA_Code: E96; SizeX_mm: 1; SizeY_mm: 0.5; SizeZ_mm: 0.6; Value2: 0.063W; AEC Qualified: Y; VDC_V: 50V; AEC Category: Q200; AEC Grade: 0
R52 R53 = CMP-0026797-1: RES, 10.0 k, 0.1%, 0.063 W, 0402; Manufacturer: TT Electronics/IRC; Power_W: 63mW; TempCo: 10 ppm/C; Value_Code: 10k0; U/M: EA; Value: 10.0k; EIA_Code: E192; Res_ohm: 10k; SizeX_mm: 1; SizeY_mm: 0.5; SizeZ_mm: 0.6; Value2: 0.063W; VDC_V: 25V; AEC Category: Q200
RS1 = CMP-0079577-1: Receptacle, D-SUB-9, 2.74mm, Gold, TH; Manufacturer: TE Connectivity; Gender: Female; Cert_UL: Y; Voltage_V: 125V; Current_A: 6A; Row_Count: 2; CompType: D-Sub
SW1 SW2 = CMP-0120713-1: Dip Switch SPST 3 Position Surface Mount Slide (Standard) Actuator 25mA 24VDC; Manufacturer: Wurth Electronics; PositionCount: 3; SizeZ_mm: 2.65mm; VDC_V: 24V; AEC Qualified: No; Coil Resistance_ohm: 100mΩ; Electromechanical Life: 2000Cycles; Standoff Height: 0mm
SW3 = CMP-0122841-1: Dip Switch SPST 1 Position Surface Mount Slide (Standard) Actuator 25mA 24VDC; Manufacturer: C&K Components; Circuit: SPST-NO; PositionCount: 1; SizeZ_mm: 2.3mm; VDC_V: 24V; AEC Qualified: No; Coil Resistance_ohm: 100mΩ; Electromechanical Life: 1000Cycles; Standoff Height: 0.1mm
SW4 = CMP-0002143-2: Switch, Tactile, SPST-NO, 0.05A, 12V, SMT; Manufacturer: E-Switch; CurrentRating_mA: 50A; PositionCount: 1; SwitchFunction: Off-Mom
U1 = CMP-0073793-1: 150-mA, 30-V, Ultra-Low IQ, Wide Input Low-Dropout Regulator with Reverse Current Protection, DBV0005A (SOT-23-5); Alternate PartNumber: TPS70933DBVT; Alternate Manufacturer: Texas Instruments; Green_Lifecycle: Active; SizeAreaWB_mm2: 14.82; Green_REACh: Passed; U/M: EA; SizeZ_mm: 1.45; SizeX_mm: 2.8; SizeY_mm: 2.9; SizeArea_mm2: 8.12; CompType: IC
U2 = CMP-0044119-1: 3-V to 5.5-V Multichannel RS-232 Line Driver / Receiver with ±15-kV IEC ESD Protection, -40 to 85 degC, 16-Pin SSOP (DB), Green (RoHS & no Sb/Br); ESD HBM(kV): +/-15; Receivers Per Package: 2; Single Supply: TRUE; ICC(Max)(mA): 1; Supply Voltage(s)(V): 3.3 or 5.0
U3 = CMP-0128118-1: Quad, ultra-high-precision (10 μV) zero-drift (0.01 μV/°C) low-input-bias-current op amp 14-TSSOP -40 to 125; Manufacturer: Texas Instruments; SizeZ_mm: 1.2mm; AEC Qualified: No; Gain Bandwidth: 5.7MHz; Input Bias Current: 60pA; Input Offset Voltage: 1uV; Max Dual Supply Voltage: 2.75V; Max Supply Voltage: 5.5V; Min Dual Supply Voltage: 850mV; Min Supply Voltage: 1.7V; Number Of Channels: 4; Output Current Per Channel: 55mA; Response Time: 2.5us; Standoff Height: 0.05mm; TaMax_C: +125°C; TaMin_C: -40°C; TJmax_C: +150°C; Voltage Gain: 145dB
U4 = CMP-0094636-1: Manufacturer: Texas Instruments; Min Supply Voltage: 1.71V; TJmax_C: +150°C; Max Supply Voltage: 5.5V; Standoff Height: 0.1mm; TaMax_C: +125°C; SizeZ_mm: 2.65mm; Interface: SPI,CAN,RS-232,RS-485; TaMin_C: -40°C; AEC Qualified: No
U5 = CMP-0085527-2: 8-Channel, 24-Bit, Simultaneously-Sampling, Delta-Sigma ADC, PBS0032A (TQFP-32); Manufacturer: Texas Instruments; SizeZ_mm: 1.2; AEC Qualified: N; SizeArea_mm2: 49; SizeAreaWB_mm2: 81; CompType: IC; SizeX_mm: 7; AEC Category: Q200
U6 = CMP-0094692-4: Mixed-Signal Microcontrollers; Manufacturer: Texas Instruments; Frequency_Fixed: 80MHz; Number Of Timers/Counters: 7; Number Of Cores: 1; AEC Category: Q200; Data Bus Width: 32bits; Standoff Height: 0mm; Memory Type: FLASH; Number Of Uart Channels: 4; Memory Size: 64KBytes; TaMin_C: -40°C; Number Of I2C Channels: 2; Max Supply Voltage: 3.6V; SizeZ_mm: 0.9mm; CompType: IC; Interface: I2C,SPI,UART,LIN,IrDA,SMBus; Min Supply Voltage: 1.35V; AEC Qualified: No; Core Architecture: ARM Cortex-M0+; Number Of Adc Channels: 10; Ram Size: 32KBytes; Number Of I/Os: 28; TaMax_C: +105°C
Y1 = CMP-0094615-2: Crystal replacement: Ultra-low Power LVCMOS Oscillator 4-pin, VSON 3.2 x 2.5 x 0.9mm; Manufacturer: Texas Instruments; AEC Qualified: No; Standoff Height: 0mm; Min Supply Voltage: 2.375V; TaMin_C: -40°C; Load Capacitance: 15pF; Frequency Stability: 20ppm; AEC Category: Q200; Frequency_Fixed: 50MHz; CompType: IC; SizeZ_mm: 1mm; Max Supply Voltage: 3.465V; TJmax_C: +135°C; TaMax_C: +105°C; Max Supply Current: 4mA

## Sheet PCB_Project_Hardware.SchDoc
size 431 x 279 mm; Date: Not shown in title block; ApprovedBy: Not shown in title block; CheckedBy: Not shown in title block; Author: Not shown in title block; CompanyName: Not shown in title block; Engineer: Not shown in title block; Organization: Not shown in title block; Address1: Not shown in title block; Address2: Not shown in title block; Address3: Not shown in title block; Address4: Not shown in title block; DocumentNumber: 3; Revision: Use project parameter SCH_Rev; SheetNumber: 3; SheetTotal: 3; PageSetup: Record=PageOptions¦CenterHorizontal=True¦CenterVertical=True¦PrintScale=1.00¦XCorrection=1.00¦YCorrection=1.00¦PrintKind=0¦BorderSize=5000000¦LeftOffset=0¦BottomOffset=0¦Orientation=2¦PaperLength=1000¦PaperWidth=1000¦Scale=100¦PaperSource=15¦PrintQuality=600¦MediaType=1¦DitherType=10¦PaperKind=Letter¦PrintScaleMode=1
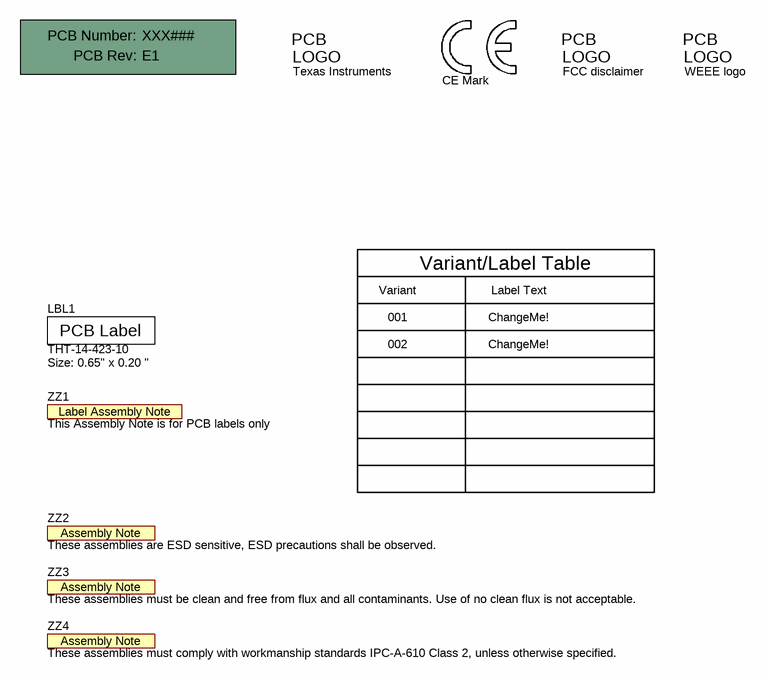
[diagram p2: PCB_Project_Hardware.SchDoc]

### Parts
!PCB  Printed Circuit Board  (value not drawn)  (mechanical)
LBL1  THT-14-423-10  Note: Size: 0.65" x 0.20 "  [Label_650x200]
Logo1  Texas Instruments  [TI_Stacked_Overlay_Small]  (no BOM)
Logo2  CE Mark  [CE_Mark_5mm]  (no BOM)
Logo3  FCC disclaimer  [FCC_disclaimer]  (no BOM)
Logo4  WEEE logo  [WEEE_Minimum]  (no BOM)
ZZ1  This Assembly Note is for PCB labels only  [AssemblyNoteLabel]  (no BOM)
ZZ2  These assemblies are ESD sensitive, ESD precautions shall be observed.  [AssemblyNote]  (no BOM)
ZZ3  These assemblies must be clean and free from flux and all contaminants. Use of no clean flux is not acceptable.  [AssemblyNote]  (no BOM)
ZZ4  These assemblies must comply with workmanship standards IPC-A-610 Class 2, unless otherwise specified.  [AssemblyNote]  (no BOM)

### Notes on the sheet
- Variant
- Variant/Label Table
- Label Text
- 001
- 002
- ChangeMe!

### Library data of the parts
!PCB = CMP-0003618-2: Manufacturer: Any; PartNumber: XXX###
LBL1 = CMP-0003625-1: Thermal Transfer Printable Labels, 0.650" W x 0.200" H - 10,000 per roll; Manufacturer: Brady; CompType: Label
Logo1 = CMP-0074838-1: Texas Instrument Corporate Signature; SymbolCreator: a0412235; Lib Reference: TI_Logo; Library Reference: Logo
Logo2 = CMP-0074844-1: SymbolCreator: a0412235
Logo3 = CMP-0074847-1: FCC_disclaimer; Library Reference: Logo
Logo4 = CMP-0074769-1
ZZ1 = CMP-0003616-3
ZZ2 = CMP-0077236-1
ZZ3 = CMP-0077237-1
ZZ4 = CMP-0077238-1

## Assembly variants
001: all parts fitted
